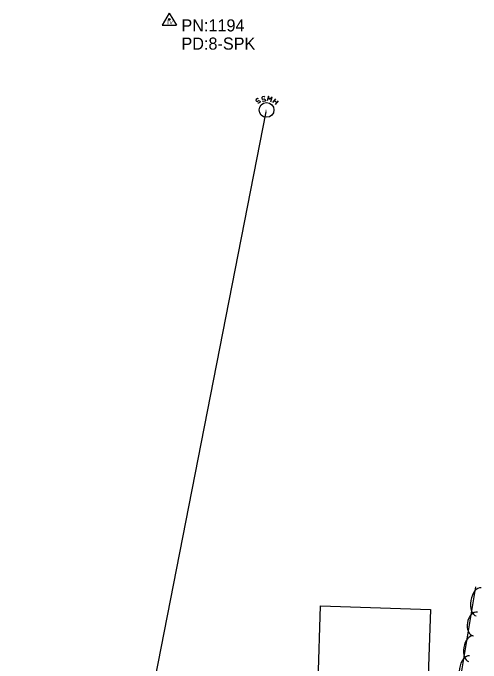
# Model space of a CAD drawing. Extents: x 978516 to 993312, y 1836504 to 1846212.
# Drawn here: x 990800.4 to 990993.4, y 1839636.5 to 1839904.5 of the extents above; entities that cross this region are included whole.
import ezdxf

# ---------------------------------------------------------------- set-up
doc = ezdxf.new("R2010")
doc.units = 0
for name, color, linetype in [('S_BUILDING', 7, 'Continuous'), ('S_SANITARY_SEWER', 7, 'Continuous'), ('S_SECONDARY_CTL', 7, 'Continuous'), ('S_SECONDARY_CTL_ANNOT', 7, 'Continuous'), ('S_TREE', 7, 'Continuous'), ('S_UTL_PT_SYM', 7, 'Continuous')]:
    doc.layers.add(name, color=color, linetype=linetype)

msp = doc.modelspace()

# ---------------------------------------------------------------- linework, layer by layer
at = {"layer": 'S_BUILDING'}
msp.add_lwpolyline([(990971.55, 1839627.41), (990926.23, 1839628.94), (990927.28, 1839660.1), (990972.6, 1839658.57)], close=True, dxfattribs=at)
at = {"layer": 'S_SANITARY_SEWER'}
for p, q in [((990900.63, 1839868.85), (990900.55, 1839868.46)), ((990900.55, 1839868.46), (990900.75, 1839868.19)), ((990901.17, 1839869.24), (990900.63, 1839868.85)), ((990900.75, 1839868.19), (990901.17, 1839868.07)), ((990901.6, 1839869.16), (990901.17, 1839869.24)), ((990901.17, 1839868.07), (990901.71, 1839868.42)), ((990901.71, 1839867.26), (990901.33, 1839867.34)), ((990901.71, 1839868.42), (990902.18, 1839868.35)), ((990902.26, 1839867.65), (990901.71, 1839867.26)), ((990902.18, 1839868.35), (990902.33, 1839868.07)), ((990902.33, 1839868.07), (990902.26, 1839867.65)), ((990907.6, 1839867.61), (990908.84, 1839869.08)), ((990908.26, 1839868.38), (990909.23, 1839867.57)), ((990909.81, 1839868.27), (990908.57, 1839866.8)), ((990800.36, 1839330.36), (990904.77, 1839863.76))]:
    msp.add_line(p, q, dxfattribs=at)
for points in [[(990904.27, 1839869.78), (990903.92, 1839870.05), (990903.26, 1839869.97), (990903.03, 1839869.62), (990903.07, 1839869.31), (990903.42, 1839869), (990904.04, 1839869.12), (990904.43, 1839868.81), (990904.47, 1839868.5), (990904.19, 1839868.11), (990903.57, 1839868.04), (990903.23, 1839868.31)], [(990906.71, 1839867.92), (990907.26, 1839869.78), (990906.21, 1839868.77), (990905.82, 1839870.21), (990905.28, 1839868.35)]]:
    msp.add_lwpolyline(points, dxfattribs=at)
msp.add_circle((990904.96, 1839864.55), 3.05, dxfattribs=at)
at = {"layer": 'S_SECONDARY_CTL'}
for p, q in [((990864.85, 1839904.5), (990861.84, 1839899.55)), ((990864.85, 1839904.5), (990867.8, 1839899.55)), ((990861.84, 1839899.55), (990867.8, 1839899.55))]:
    msp.add_line(p, q, dxfattribs=at)
for radius in [0.311, 0.183, 0.103]:
    msp.add_circle((990864.85, 1839901.89), radius, dxfattribs=at)
at = {"layer": 'S_TREE'}
msp.add_lwpolyline([(990983.26, 1839620.01), (990991.35, 1839667.86)], dxfattribs=at)
for centre, major_axis, ratio in [((990992.46, 1839661.71), (-0.98, -5.79), 0.55008), ((990991.17, 1839652.54), (-0.83, -4.89), 0.685311), ((990989.2, 1839642.42), (-0.89, -5.27), 0.540699), ((990987.72, 1839633.68), (-0.98, -5.79), 0.55008)]:
    msp.add_ellipse(centre, major_axis=major_axis, ratio=ratio, start_param=3.141593, end_param=6.283185, dxfattribs=at)
at = {"layer": 'S_UTL_PT_SYM'}
for points in [[(990904.77, 1839864.31), (990904.77, 1839864.36), (990904.77, 1839864.31), (990904.72, 1839864.31), (990904.77, 1839864.31), (990904.77, 1839864.26), (990904.77, 1839864.31), (990904.82, 1839864.31)], [(990904.77, 1839863.76), (990904.77, 1839863.81), (990904.77, 1839863.76), (990904.72, 1839863.76), (990904.77, 1839863.76), (990904.77, 1839863.71), (990904.77, 1839863.76), (990904.82, 1839863.76)]]:
    msp.add_lwpolyline(points, dxfattribs=at)

# ---------------------------------------------------------------- texts
at = {"layer": 'S_SECONDARY_CTL'}
msp.add_text('TV', height=1.5, dxfattribs=at).set_placement((990863.65, 1839899.88))
at = {"layer": 'S_SECONDARY_CTL_ANNOT'}
for s, p in [('PN:1194', (990869.85, 1839896.89)), ('PD:8-SPK', (990869.85, 1839889.39))]:
    msp.add_text(s, height=5, dxfattribs=at).set_placement(p)

doc.saveas('drawing.dxf')
